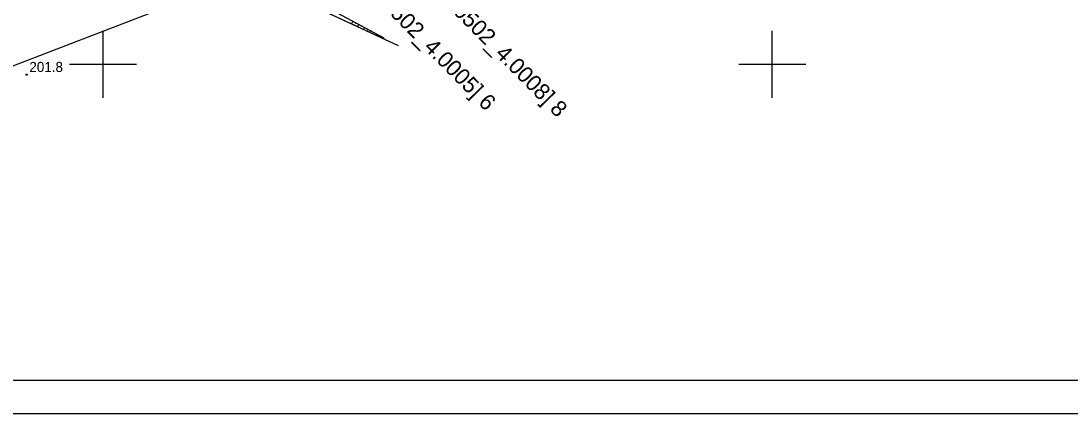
# Model space of a CAD drawing. Extents: x 6512606 to 6513006, y 6022524 to 6022728.
# Drawn here: x 6512793.9 to 6512872.3, y 6022523.9 to 6022553.2 of the extents above; entities that cross this region are included whole.
import ezdxf

# ---------------------------------------------------------------- set-up
doc = ezdxf.new("R2010")
doc.units = 0
for name, color, linetype in [('000 Inne (niezydentyfikowane)', 7, 'Continuous'), ('208-opis obrębu', 7, 'Continuous'), ('Default', 7, 'Continuous'), ('maxp_ramka_2', 7, 'Continuous'), ('Obszar opracowania', 7, 'Continuous'), ('pikieta naturalna', 7, 'Continuous'), ('pikieta naturalna-Atr2', 7, 'Continuous'), ('skarpa nieumocniona', 7, 'Continuous'), ('woda stojąca', 7, 'Continuous')]:
    doc.layers.add(name, color=color, linetype=linetype)

# ---------------------------------------------------------------- blocks, each defined once
blk = doc.blocks.new('PW01')
at = {"layer": 'Default'}
blk.add_circle((0, 0), 0.45, dxfattribs=at)

msp = doc.modelspace()

# ---------------------------------------------------------------- linework, layer by layer
at = {"layer": '000 Inne (niezydentyfikowane)'}
for p, q in [((6512818.65, 6022553.22), (6512818.55, 6022553.02)), ((6512818.88, 6022553.1), (6512818.83, 6022553.01)), ((6512819.1, 6022552.98), (6512819.01, 6022552.81)), ((6512819.32, 6022552.86), (6512819.28, 6022552.78)), ((6512819.54, 6022552.74), (6512819.46, 6022552.59)), ((6512819.77, 6022552.62), (6512819.73, 6022552.55)), ((6512819.99, 6022552.5), (6512819.92, 6022552.38)), ((6512820.21, 6022552.38), (6512820.18, 6022552.33)), ((6512820.43, 6022552.26), (6512820.38, 6022552.17)), ((6512820.65, 6022552.14), (6512820.63, 6022552.1)), ((6512820.88, 6022552.03), (6512820.84, 6022551.96))]:
    msp.add_line(p, q, dxfattribs=at)
at = {"layer": 'Default'}
for p, q in [((6512800, 6022547.5), (6512800, 6022552.5)), ((6512800, 6022547.5), (6512800, 6022552.5)), ((6512850, 6022547.5), (6512850, 6022552.5)), ((6512797.5, 6022550), (6512800, 6022550)), ((6512800, 6022550), (6512802.5, 6022550)), ((6512847.5, 6022550), (6512852.5, 6022550))]:
    msp.add_line(p, q, dxfattribs=at)
at = {"layer": 'maxp_ramka_2'}
for points in [[(6512605.658, 6022723.882), (6513005.658, 6022723.882), (6513005.658, 6022523.882), (6512605.658, 6022523.882)], [(6512618.158, 6022526.382), (6512618.158, 6022721.382), (6513003.158, 6022721.382), (6513003.158, 6022526.382)]]:
    msp.add_lwpolyline(points, close=True, dxfattribs=at)
at = {"layer": 'Obszar opracowania'}
msp.add_lwpolyline([(6512710.98, 6022693.84), (6512748.35, 6022694.16), (6512798.11, 6022695.25), (6512807.47, 6022695.46), (6512809.66, 6022606.87), (6512863.71, 6022622.03), (6512875.13, 6022581.36), (6512755.22, 6022535.25), (6512691.61, 6022568.03), (6512709.16, 6022605.16)], close=True, dxfattribs=at)
at = {"layer": 'skarpa nieumocniona'}
msp.add_lwpolyline([(6512800.44, 6022571.24), (6512803.01, 6022568.94), (6512806.7, 6022559.63), (6512820.98, 6022551.97), (6512820.89, 6022551.93), (6512805.27, 6022559.18), (6512802.35, 6022567.67), (6512799.36, 6022570.79), (6512795.57, 6022571.66), (6512797.5, 6022572.25)], close=True, dxfattribs=at)
msp.add_lwpolyline([(6512800.44, 6022571.24), (6512803.01, 6022568.94), (6512806.7, 6022559.63), (6512820.98, 6022551.97), (6512820.89, 6022551.93), (6512805.27, 6022559.18), (6512802.35, 6022567.67), (6512799.36, 6022570.79), (6512795.57, 6022571.66), (6512797.5, 6022572.25)], close=True, dxfattribs=at)
at = {"layer": 'woda stojąca'}
msp.add_lwpolyline([(6512822.08, 6022551.38), (6512805.27, 6022559.18), (6512802.35, 6022567.67), (6512799.36, 6022570.79), (6512795.57, 6022571.66), (6512793.8, 6022570.72), (6512788.79, 6022572.53), (6512778.27, 6022575.8), (6512775.8, 6022576.99), (6512772.41, 6022579.75), (6512771.62, 6022580.04), (6512770.3, 6022579.81), (6512769.49, 6022580.02), (6512768.52, 6022578.94)], dxfattribs=at)

# ---------------------------------------------------------------- block references
at = {"layer": 'pikieta naturalna', "xscale": 0.1, "yscale": 0.10000000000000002}
msp.add_blockref('PW01', (6512794.29, 6022549.22), dxfattribs=at)

# ---------------------------------------------------------------- texts
at = {"layer": '208-opis obrębu'}
for s, p in [('[220502_4.0005] 6', (6512819.19, 6022555.96)), ('[220502_4.0008] 8', (6512824.53, 6022555.47))]:
    msp.add_text(s, height=1.2, rotation=314.681, dxfattribs=at).set_placement(p)
at = {"layer": 'pikieta naturalna-Atr2'}
msp.add_text('201.8', height=0.75, dxfattribs=at).set_placement((6512794.49, 6022549.42))

doc.saveas('drawing.dxf')
